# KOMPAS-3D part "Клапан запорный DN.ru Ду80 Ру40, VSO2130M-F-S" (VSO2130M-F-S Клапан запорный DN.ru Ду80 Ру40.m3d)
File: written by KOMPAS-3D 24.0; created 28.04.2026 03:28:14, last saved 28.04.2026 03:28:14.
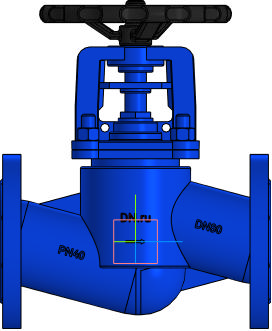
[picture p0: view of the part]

Document properties: Автор: DN.ru; Полное имя файла: C:\Работа\ГОТОВЫЕ ИСХОДНИКИ\VSO2130M-F-S Клапан запорный сильфонный DN.ru Ду15-100 Ру40\DN80\VSO2130M-F-S Клапан запорный DN.ru Ду80 Ру40.m3d

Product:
- Part/product: Клапан запорный DN.ru Ду80 Ру40  | designation VSO2130M-F-S
    Масса: 22
    Раздел спецификации: Прочие изделия
    Примечание: D090-01977

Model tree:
1. Операция без истории:1

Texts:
  VSO2130M-F-S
